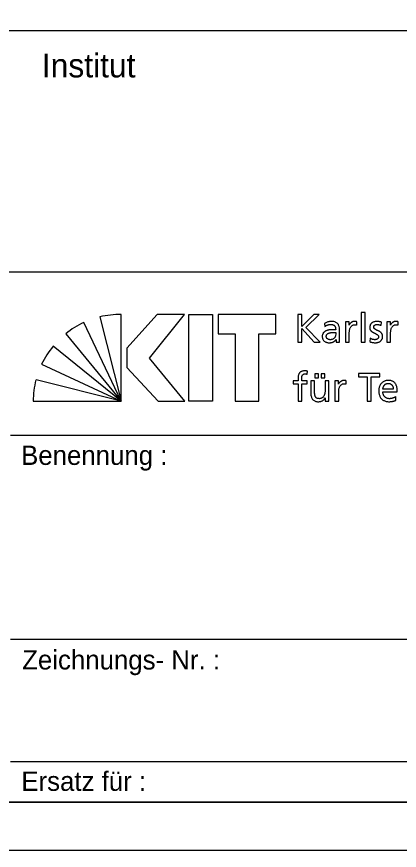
# Model space of a CAD drawing. Extents: x 0 to 16.8, y 0 to 11.9.
# Drawn here: x 15.053 to 15.847, y 0 to 1.73 of the extents above; entities that cross this region are included whole.
import ezdxf

# ---------------------------------------------------------------- set-up
doc = ezdxf.new("R2010")
doc.units = 0
doc.layers.add('90_Plankopf', color=7, linetype='Continuous')

msp = doc.modelspace()

# ---------------------------------------------------------------- linework, layer by layer
at = {"layer": '90_Plankopf'}
for p, q in [((16.72, 1.6998), (13.1624, 1.6998)), ((13.1624, 1.1998), (16.72, 1.1998)), ((13.1624, 1.1998), (16.72, 1.1998)), ((15.2696, 0.9317), (15.2696, 1.1117)), ((15.6362, 1.1117), (15.6362, 1.0541)), ((15.2696, 0.9317), (15.1927, 1.095)), ((15.2255, 1.1067), (15.2696, 0.9317)), ((15.6916, 1.0932), (15.692, 1.0866)), ((15.7585, 1.0897), (15.7585, 1.0966)), ((15.8091, 1.0888), (15.8098, 1.0956)), ((15.8442, 1.0897), (15.8442, 1.0966)), ((15.7146, 1.0742), (15.7146, 1.0705)), ((15.7224, 1.0624), (15.7224, 1.0798)), ((15.1549, 1.0717), (15.2696, 0.9317)), ((15.7859, 1.0624), (15.7855, 1.0554)), ((15.2696, 0.9317), (15.1287, 1.0457)), ((15.6362, 1.0541), (15.6444, 1.0541)), ((15.6701, 1.0541), (15.6822, 1.0541)), ((15.1048, 1.0083), (15.2696, 0.9317)), ((15.6555, 0.9879), (15.6558, 0.9941)), ((15.2696, 0.9317), (15.0932, 0.9758)), ((15.7365, 0.9673), (15.7365, 0.9742)), ((15.8341, 0.9568), (15.8123, 0.9568)), ((15.8123, 0.951), (15.8424, 0.951)), ((15.8392, 0.9335), (15.8392, 0.9412)), ((15.0873, 0.9317), (15.2696, 0.9317)), ((15.04, 0.8614), (16.72, 0.8614)), ((15.04, 0.4384), (16.72, 0.4384)), ((15.04, 0.1846), (16.72, 0.1846)), ((16.72, 0.1), (13.1624, 0.1)), ((13.396, 0.1), (16.72, 0.1)), ((13.396, 0.1), (16.72, 0.1))]:
    msp.add_line(p, q, dxfattribs=at)
for points in [[(0, 0), (16.82, 0), (16.82, 11.88), (0, 11.88)], [(0.5, 11.78), (16.72, 11.78), (16.72, 0.1), (0.5, 0.1)], [(15.4013, 1.1117), (15.3447, 1.1117), (15.2815, 1.042), (15.2815, 1.0018), (15.3468, 0.9317), (15.4017, 0.9317), (15.3284, 1.0213)], [(15.4594, 1.1117), (15.4594, 0.9317), (15.41, 0.9317), (15.41, 1.1117)], [(15.4712, 1.1117), (15.4712, 1.0712), (15.506, 1.0712), (15.506, 0.9317), (15.5554, 0.9317), (15.5554, 1.0712), (15.5902, 1.0712), (15.5902, 1.1117)]]:
    msp.add_lwpolyline(points, close=True, dxfattribs=at)
for points in [[(15.6822, 1.0541), (15.6529, 1.0845), (15.68, 1.1117), (15.669, 1.1117), (15.6444, 1.0864), (15.6444, 1.1117), (15.6362, 1.1117)], [(15.7676, 1.0541), (15.7754, 1.0541), (15.7754, 1.116), (15.7676, 1.116), (15.7676, 1.0541)], [(15.7424, 1.0897), (15.7423, 1.0897), (15.7423, 1.0962), (15.735, 1.0962), (15.735, 1.0541), (15.7428, 1.0541), (15.7428, 1.0733)], [(15.8281, 1.0897), (15.828, 1.0897), (15.828, 1.0962), (15.8207, 1.0962), (15.8207, 1.0541), (15.8285, 1.0541), (15.8285, 1.0733)], [(15.6444, 1.0541), (15.6444, 1.0823), (15.6701, 1.0541)], [(15.7153, 1.0596), (15.7154, 1.0596), (15.7154, 1.0541), (15.7227, 1.0541)], [(15.6711, 0.9885), (15.6711, 0.9803), (15.6788, 0.9803), (15.6788, 0.9885), (15.6711, 0.9885)], [(15.6846, 0.9885), (15.6846, 0.9803), (15.6924, 0.9803), (15.6924, 0.9885), (15.6846, 0.9885)], [(15.7798, 0.9317), (15.7881, 0.9317), (15.7881, 0.9821), (15.806, 0.9821), (15.806, 0.9893), (15.7619, 0.9893), (15.7619, 0.9821), (15.7798, 0.9821), (15.7798, 0.9317)], [(15.6365, 0.9777), (15.6365, 0.9738), (15.6266, 0.9738), (15.6266, 0.9676), (15.6365, 0.9676), (15.6365, 0.9317), (15.6442, 0.9317), (15.6442, 0.9676), (15.6554, 0.9676), (15.6554, 0.9738), (15.6442, 0.9738), (15.6442, 0.9784)], [(15.6708, 0.952), (15.6708, 0.9738), (15.6631, 0.9738), (15.6631, 0.9488)], [(15.7003, 0.9317), (15.7003, 0.9738), (15.6925, 0.9738), (15.6925, 0.9543)], [(15.7204, 0.9673), (15.7203, 0.9673), (15.7203, 0.9738), (15.713, 0.9738), (15.713, 0.9317), (15.7208, 0.9317), (15.7208, 0.9509)], [(15.6926, 0.9384), (15.6928, 0.9384), (15.6928, 0.9317), (15.7003, 0.9317)]]:
    msp.add_lwpolyline(points, dxfattribs=at)
for centre, start, end in [((15.269, 0.9211), 89.8053, 103.1895), ((15.2732, 0.9224), 115.0126, 128.3968), ((15.2763, 0.9253), 140.7898, 154.174), ((15.2778, 0.9288), 165.7222, 179.1064)]:
    msp.add_arc(centre, 0.1906, start, end, dxfattribs=at)
for points in [[(15.7224, 1.0798), (15.7224, 1.0836), (15.7218, 1.0868), (15.7207, 1.0894), (15.7195, 1.092), (15.7177, 1.0939), (15.7152, 1.0952), (15.7127, 1.0965), (15.7094, 1.0972), (15.7054, 1.0972), (15.7028, 1.0972), (15.7003, 1.0968), (15.698, 1.0961), (15.6956, 1.0954), (15.6935, 1.0944), (15.6916, 1.0932)], [(15.692, 1.0866), (15.6931, 1.0875), (15.6943, 1.0883), (15.6956, 1.0889), (15.6969, 1.0896), (15.6983, 1.0901), (15.6998, 1.0904), (15.7013, 1.0908), (15.7027, 1.0909), (15.7042, 1.0909), (15.7068, 1.0909), (15.7088, 1.0905), (15.7104, 1.0897), (15.7119, 1.0889), (15.713, 1.0877), (15.7136, 1.086), (15.7143, 1.0844), (15.7146, 1.0824), (15.7146, 1.0799)], [(15.7585, 1.0966), (15.758, 1.0967), (15.7575, 1.0968), (15.757, 1.0969), (15.7565, 1.097), (15.756, 1.0971), (15.7554, 1.0971), (15.7548, 1.0972), (15.7542, 1.0972), (15.7534, 1.0972), (15.7519, 1.0972), (15.7505, 1.0969), (15.749, 1.0962), (15.7476, 1.0956), (15.7464, 1.0947), (15.7452, 1.0936), (15.7441, 1.0925), (15.7431, 1.0912), (15.7424, 1.0897)], [(15.7428, 1.0733), (15.7428, 1.0768), (15.7433, 1.0799), (15.7442, 1.0824), (15.7451, 1.085), (15.7465, 1.087), (15.7482, 1.0883), (15.7499, 1.0897), (15.7519, 1.0904), (15.7542, 1.0904), (15.7549, 1.0904), (15.7556, 1.0904), (15.7564, 1.0903), (15.7571, 1.0902), (15.7578, 1.09), (15.7585, 1.0897)], [(15.8098, 1.0956), (15.8083, 1.096), (15.8067, 1.0964), (15.8052, 1.0967), (15.8036, 1.097), (15.8019, 1.0972), (15.8001, 1.0972), (15.7981, 1.0972), (15.7961, 1.0969), (15.7943, 1.0964), (15.7925, 1.0959), (15.7909, 1.0951), (15.7896, 1.094), (15.7882, 1.0929), (15.7872, 1.0916), (15.7864, 1.09), (15.7857, 1.0883), (15.7853, 1.0864), (15.7853, 1.0842), (15.7853, 1.0826), (15.7856, 1.0811), (15.7863, 1.0799), (15.7869, 1.0787), (15.7878, 1.0776), (15.7889, 1.0767), (15.79, 1.0758), (15.7912, 1.075), (15.7925, 1.0743), (15.7938, 1.0736), (15.7951, 1.0729), (15.7963, 1.0723), (15.7976, 1.0717), (15.7988, 1.0711), (15.7999, 1.0704), (15.801, 1.0698), (15.8019, 1.0691), (15.8025, 1.0683), (15.8032, 1.0675), (15.8035, 1.0665), (15.8035, 1.0654), (15.8035, 1.0643), (15.8033, 1.0633), (15.8028, 1.0626), (15.8023, 1.0618), (15.8017, 1.0612), (15.8009, 1.0607), (15.8001, 1.0602), (15.7993, 1.0599), (15.7983, 1.0597), (15.7974, 1.0595), (15.7965, 1.0594), (15.7956, 1.0594), (15.7948, 1.0594), (15.7939, 1.0595), (15.7928, 1.0597), (15.7917, 1.0599), (15.7905, 1.0603), (15.7893, 1.0607), (15.7881, 1.0612), (15.787, 1.0617), (15.7859, 1.0624)], [(15.7855, 1.0554), (15.7873, 1.0545), (15.7892, 1.0539), (15.7912, 1.0536), (15.7931, 1.0532), (15.7951, 1.0531), (15.7971, 1.0531), (15.799, 1.0531), (15.8008, 1.0534), (15.8025, 1.0539), (15.8043, 1.0544), (15.8059, 1.0552), (15.8073, 1.0563), (15.8086, 1.0574), (15.8097, 1.0588), (15.8105, 1.0604), (15.8114, 1.0621), (15.8118, 1.064), (15.8118, 1.0662), (15.8118, 1.0682), (15.8114, 1.0698), (15.8108, 1.0711), (15.8101, 1.0724), (15.8092, 1.0736), (15.8082, 1.0745), (15.8071, 1.0754), (15.8059, 1.0762), (15.8046, 1.0769), (15.8033, 1.0776), (15.802, 1.0782), (15.8007, 1.0787), (15.7994, 1.0793), (15.7982, 1.0799), (15.7972, 1.0805), (15.7961, 1.0812), (15.7952, 1.0819), (15.7945, 1.0827), (15.7939, 1.0836), (15.7936, 1.0846), (15.7935, 1.0858), (15.7936, 1.087), (15.7939, 1.0879), (15.7946, 1.0887), (15.7953, 1.0894), (15.7962, 1.09), (15.7973, 1.0904), (15.7984, 1.0908), (15.7996, 1.0909), (15.801, 1.0909), (15.8014, 1.0909), (15.802, 1.0909), (15.8028, 1.0908), (15.8035, 1.0906), (15.8043, 1.0905), (15.8051, 1.0903), (15.8059, 1.0901), (15.8067, 1.0898), (15.8074, 1.0896), (15.8081, 1.0893), (15.8087, 1.0891), (15.8091, 1.0888)], [(15.8442, 1.0966), (15.8437, 1.0967), (15.8432, 1.0968), (15.8427, 1.0969), (15.8422, 1.097), (15.8417, 1.0971), (15.8411, 1.0971), (15.8405, 1.0972), (15.8399, 1.0972), (15.8391, 1.0972), (15.8376, 1.0972), (15.8362, 1.0969), (15.8347, 1.0962), (15.8333, 1.0956), (15.8321, 1.0947), (15.8309, 1.0936), (15.8298, 1.0925), (15.8288, 1.0912), (15.8281, 1.0897)], [(15.8285, 1.0733), (15.8285, 1.0768), (15.829, 1.0799), (15.8299, 1.0824), (15.8308, 1.085), (15.8322, 1.087), (15.8339, 1.0883), (15.8356, 1.0897), (15.8376, 1.0904), (15.8399, 1.0904), (15.8406, 1.0904), (15.8413, 1.0904), (15.8421, 1.0903), (15.8428, 1.0902), (15.8435, 1.09), (15.8442, 1.0897)], [(15.7146, 1.0799), (15.7136, 1.08), (15.7127, 1.08), (15.7118, 1.0801), (15.7109, 1.0801), (15.71, 1.0801), (15.7092, 1.0801), (15.7083, 1.0801), (15.7074, 1.0801), (15.7064, 1.0801), (15.7047, 1.0801), (15.703, 1.08), (15.7013, 1.0797), (15.6995, 1.0794), (15.6977, 1.0789), (15.696, 1.0783), (15.6943, 1.0776), (15.6928, 1.0768), (15.6914, 1.0757), (15.69, 1.0746), (15.6889, 1.0733), (15.6881, 1.0718), (15.6872, 1.0702), (15.6868, 1.0684), (15.6868, 1.0662), (15.6868, 1.0632), (15.6875, 1.0607), (15.6888, 1.0588), (15.6901, 1.0568), (15.6919, 1.0554), (15.6942, 1.0545), (15.6965, 1.0536), (15.6992, 1.0531), (15.7022, 1.0531), (15.704, 1.0531), (15.7056, 1.0534), (15.707, 1.0538), (15.7084, 1.0542), (15.7097, 1.0547), (15.7107, 1.0554), (15.7118, 1.056), (15.7127, 1.0567), (15.7135, 1.0575), (15.7142, 1.0582), (15.7148, 1.0589), (15.7153, 1.0596)], [(15.7146, 1.0705), (15.7146, 1.0684), (15.7142, 1.0665), (15.7133, 1.0648), (15.7124, 1.0631), (15.7111, 1.0618), (15.7093, 1.0609), (15.7076, 1.0599), (15.7054, 1.0594), (15.7029, 1.0594), (15.702, 1.0594), (15.7011, 1.0596), (15.7002, 1.0598), (15.6993, 1.0601), (15.6984, 1.0606), (15.6976, 1.0611), (15.6969, 1.0617), (15.6962, 1.0625), (15.6958, 1.0633), (15.6953, 1.0641), (15.6951, 1.0651), (15.695, 1.0662), (15.6951, 1.0677), (15.6954, 1.069), (15.6962, 1.0699), (15.6969, 1.0709), (15.6978, 1.0717), (15.699, 1.0723), (15.7001, 1.0729), (15.7014, 1.0733), (15.7027, 1.0736), (15.704, 1.0739), (15.7053, 1.0741), (15.7065, 1.0742), (15.7077, 1.0743), (15.7088, 1.0743), (15.7097, 1.0743), (15.7105, 1.0743), (15.7113, 1.0743), (15.7121, 1.0743), (15.713, 1.0742), (15.7138, 1.0742), (15.7146, 1.0742)], [(15.7227, 1.0541), (15.7226, 1.0545), (15.7226, 1.0551), (15.7225, 1.0557), (15.7225, 1.0564), (15.7224, 1.0573), (15.7224, 1.0584), (15.7224, 1.0595), (15.7224, 1.0608), (15.7224, 1.0624)], [(15.6558, 0.9941), (15.655, 0.9942), (15.6542, 0.9944), (15.6534, 0.9945), (15.6525, 0.9946), (15.6516, 0.9946), (15.6506, 0.9946), (15.6478, 0.9946), (15.6454, 0.9942), (15.6436, 0.9934), (15.6417, 0.9926), (15.6403, 0.9915), (15.6392, 0.99), (15.6382, 0.9885), (15.6375, 0.9867), (15.6371, 0.9847), (15.6367, 0.9826), (15.6365, 0.9803), (15.6365, 0.9777)], [(15.6442, 0.9784), (15.6442, 0.9798), (15.6443, 0.9811), (15.6445, 0.9823), (15.6446, 0.9835), (15.645, 0.9846), (15.6455, 0.9855), (15.646, 0.9864), (15.6468, 0.9871), (15.6478, 0.9876), (15.6488, 0.9881), (15.6501, 0.9883), (15.6518, 0.9883), (15.6524, 0.9883), (15.6531, 0.9883), (15.6538, 0.9882), (15.6544, 0.9881), (15.655, 0.988), (15.6555, 0.9879)], [(15.7365, 0.9742), (15.736, 0.9743), (15.7355, 0.9744), (15.735, 0.9745), (15.7345, 0.9746), (15.734, 0.9747), (15.7334, 0.9747), (15.7328, 0.9748), (15.7322, 0.9748), (15.7314, 0.9748), (15.7299, 0.9748), (15.7285, 0.9745), (15.727, 0.9738), (15.7256, 0.9732), (15.7244, 0.9723), (15.7232, 0.9712), (15.7221, 0.9701), (15.7211, 0.9688), (15.7204, 0.9673)], [(15.8424, 0.951), (15.8424, 0.9544), (15.8421, 0.9576), (15.8414, 0.9605), (15.8408, 0.9634), (15.8398, 0.9659), (15.8384, 0.968), (15.8369, 0.9701), (15.835, 0.9718), (15.8326, 0.973), (15.8302, 0.9742), (15.8273, 0.9748), (15.8238, 0.9748), (15.8208, 0.9748), (15.8181, 0.9743), (15.8157, 0.9732), (15.8133, 0.9722), (15.8112, 0.9707), (15.8095, 0.9688), (15.8077, 0.9669), (15.8064, 0.9647), (15.8055, 0.9621), (15.8046, 0.9595), (15.8041, 0.9567), (15.8041, 0.9535), (15.8041, 0.9501), (15.8045, 0.947), (15.8054, 0.9442), (15.8062, 0.9414), (15.8076, 0.939), (15.8094, 0.937), (15.8112, 0.935), (15.8134, 0.9334), (15.8162, 0.9324), (15.8189, 0.9313), (15.8221, 0.9308), (15.8259, 0.9307), (15.8282, 0.9308), (15.8301, 0.9309), (15.8317, 0.9312), (15.8333, 0.9315), (15.8347, 0.9319), (15.8359, 0.9323), (15.8371, 0.9327), (15.8382, 0.9331), (15.8392, 0.9335)], [(15.8123, 0.9568), (15.8125, 0.9582), (15.8128, 0.9596), (15.8133, 0.9609), (15.8138, 0.9623), (15.8144, 0.9636), (15.8154, 0.9647), (15.8162, 0.9659), (15.8174, 0.9668), (15.8187, 0.9675), (15.8201, 0.9682), (15.8217, 0.9685), (15.8236, 0.9685), (15.8253, 0.9685), (15.8268, 0.9682), (15.8281, 0.9676), (15.8294, 0.967), (15.8305, 0.9662), (15.8314, 0.9651), (15.8323, 0.964), (15.833, 0.9628), (15.8334, 0.9614), (15.8339, 0.96), (15.8341, 0.9584), (15.8341, 0.9568)], [(15.6925, 0.9543), (15.6925, 0.9518), (15.6923, 0.9494), (15.6918, 0.9473), (15.6913, 0.9452), (15.6905, 0.9434), (15.6895, 0.9418), (15.6884, 0.9403), (15.6871, 0.9391), (15.6855, 0.9383), (15.6839, 0.9374), (15.6819, 0.937), (15.6797, 0.937), (15.6775, 0.9371), (15.6757, 0.9378), (15.6744, 0.9389), (15.6731, 0.94), (15.6722, 0.9417), (15.6716, 0.9439), (15.6711, 0.946), (15.6708, 0.9488), (15.6708, 0.952)], [(15.7208, 0.9509), (15.7208, 0.9544), (15.7213, 0.9575), (15.7222, 0.96), (15.7232, 0.9626), (15.7245, 0.9646), (15.7262, 0.9659), (15.7279, 0.9673), (15.7299, 0.968), (15.7322, 0.968), (15.7329, 0.9681), (15.7336, 0.968), (15.7344, 0.9679), (15.7351, 0.9678), (15.7358, 0.9676), (15.7365, 0.9673)], [(15.6631, 0.9488), (15.6631, 0.945), (15.6636, 0.9418), (15.6647, 0.9391), (15.6659, 0.9364), (15.6676, 0.9343), (15.6699, 0.9329), (15.6722, 0.9315), (15.6752, 0.9308), (15.6788, 0.9307), (15.6808, 0.9308), (15.6827, 0.9311), (15.6845, 0.9317), (15.6863, 0.9323), (15.6879, 0.9332), (15.6893, 0.9343), (15.6907, 0.9354), (15.6918, 0.9368), (15.6926, 0.9384)], [(15.8392, 0.9412), (15.8387, 0.9408), (15.838, 0.9404), (15.837, 0.9399), (15.8361, 0.9394), (15.8351, 0.939), (15.8339, 0.9385), (15.8327, 0.9381), (15.8314, 0.9377), (15.8301, 0.9374), (15.8288, 0.9372), (15.8275, 0.937), (15.8262, 0.937), (15.8243, 0.937), (15.8226, 0.9374), (15.8209, 0.938), (15.8193, 0.9387), (15.8178, 0.9397), (15.8165, 0.9409), (15.8152, 0.9421), (15.8142, 0.9436), (15.8135, 0.9453), (15.8127, 0.9471), (15.8123, 0.949), (15.8123, 0.951)]]:
    msp.add_open_spline(points, degree=3, dxfattribs=at)

# ---------------------------------------------------------------- texts
for s, height, p in [('Institut', 0.04928, (15.1053, 1.6035)), ('Benennung :', 0.04, (15.0623, 0.7996)), ('Zeichnungs- Nr. :', 0.04, (15.0645, 0.3752)), ('Ersatz für :', 0.04, (15.0628, 0.1234))]:
    msp.add_text(s, height=height, dxfattribs=at).set_placement(p)

doc.saveas('drawing.dxf')
